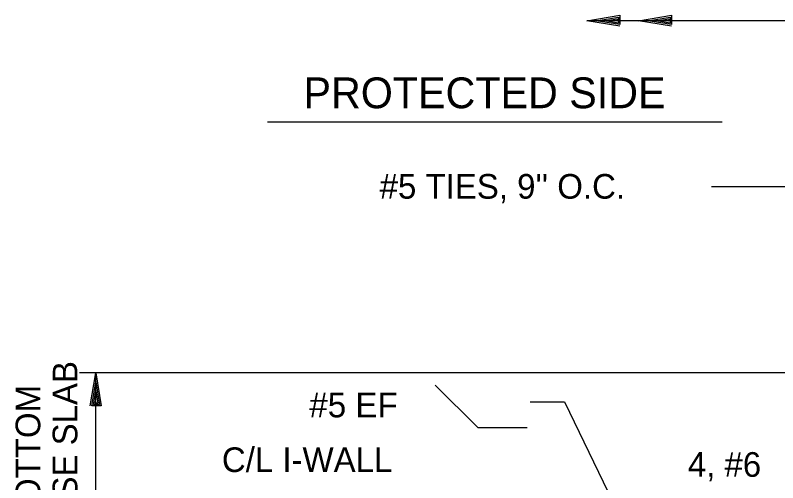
# Model space of a CAD drawing. Extents: x 22369.6 to 22428.3, y 22369.6 to 22415.
# Drawn here: x 22403.75 to 22409.49, y 22380.81 to 22384.33 of the extents above; entities that cross this region are included whole.
import ezdxf

# ---------------------------------------------------------------- set-up
doc = ezdxf.new("R2010")
doc.units = 0
for name, color, linetype in [('Level 1', 7, 'Continuous'), ('Level 10', 7, 'Continuous'), ('Level 4', 7, 'Continuous')]:
    doc.layers.add(name, color=color, linetype=linetype)

msp = doc.modelspace()

# ---------------------------------------------------------------- linework, layer by layer
at = {"layer": 'Level 1'}
for p, q in [((22411.8975, 22384.2853), (22408.0541, 22384.2853)), ((22408.0541, 22384.2853), (22408.0541, 22384.2853)), ((22408.1234, 22384.2853), (22408.1234, 22384.2853)), ((22408.6487, 22384.2853), (22408.6487, 22384.2853)), ((22408.6714, 22384.3), (22408.6714, 22384.3)), ((22408.6821, 22384.3133), (22408.6821, 22384.3133)), ((22408.6927, 22384.3266), (22408.6927, 22384.3266)), ((22408.6714, 22384.2813), (22408.6714, 22384.2813)), ((22408.6821, 22384.268), (22408.6821, 22384.268)), ((22408.6927, 22384.256), (22408.6927, 22384.256)), ((22408.6927, 22384.244), (22408.6927, 22384.244)), ((22410.1507, 22381.6336), (22404.234, 22381.6336)), ((22404.3565, 22377.6536), (22404.3565, 22381.6336)), ((22404.3565, 22381.6336), (22404.3565, 22381.6336)), ((22404.3565, 22381.5643), (22404.3565, 22381.5643))]:
    msp.add_line(p, q, dxfattribs=at)
for points in [[(22408.3034, 22384.244), (22408.0541, 22384.2853), (22408.3034, 22384.3266), (22408.3034, 22384.256), (22408.1234, 22384.2853), (22408.2927, 22384.3133), (22408.2927, 22384.268), (22408.1901, 22384.2853), (22408.2821, 22384.3), (22408.2821, 22384.2813), (22408.2594, 22384.2853)], [(22408.6927, 22384.244), (22408.4434, 22384.2853), (22408.6927, 22384.3266), (22408.6927, 22384.256), (22408.5127, 22384.2853), (22408.6821, 22384.3133), (22408.6821, 22384.268), (22408.5794, 22384.2853), (22408.6714, 22384.3), (22408.6714, 22384.2813), (22408.6487, 22384.2853)], [(22408.9934, 22383.0371), (22409.8482, 22383.0371), (22411.147, 22381.3275)], [(22404.3152, 22381.3843), (22404.3565, 22381.6336), (22404.3979, 22381.3843), (22404.3272, 22381.3843), (22404.3565, 22381.5643), (22404.3845, 22381.395), (22404.3392, 22381.395), (22404.3565, 22381.4976), (22404.3712, 22381.4056), (22404.3525, 22381.4056), (22404.3565, 22381.4283)], [(22407.6267, 22381.4145), (22407.8863, 22381.4145), (22408.5786, 22379.9799)]]:
    msp.add_lwpolyline(points, dxfattribs=at)
at = {"layer": 'Level 10'}
for p, q in [((22405.6501, 22383.5226), (22409.0738, 22383.5226)), ((22407.2332, 22381.2203), (22406.9125, 22381.541)), ((22407.2332, 22381.2203), (22407.605, 22381.2203))]:
    msp.add_line(p, q, dxfattribs=at)

# ---------------------------------------------------------------- texts
msp.add_text('PROTECTED SIDE', height=0.232168, dxfattribs=at).set_placement((22405.9211, 22383.6262))
at = {"layer": 'Level 4'}
for s, height, p in [("#5 TIES, 9'' O.C.", 0.185732, (22406.4943, 22382.9449)), ('#5 EF', 0.18667, (22405.9648, 22381.2978)), ('C/L I-WALL', 0.18573, (22405.3064, 22380.8858)), ('4, #6', 0.18574, (22408.8146, 22380.8498))]:
    msp.add_text(s, height=height, dxfattribs=at).set_placement(p)
for s, p in [('AND TOP OF ADJACENT BASE SLAB', (22404.2179, 22377.389)), ('WIDEN I-WALL BETWEEN BOTTOM', (22403.9389, 22377.389))]:
    msp.add_text(s, height=0.185698, rotation=90, dxfattribs=at).set_placement(p)

doc.saveas('drawing.dxf')
